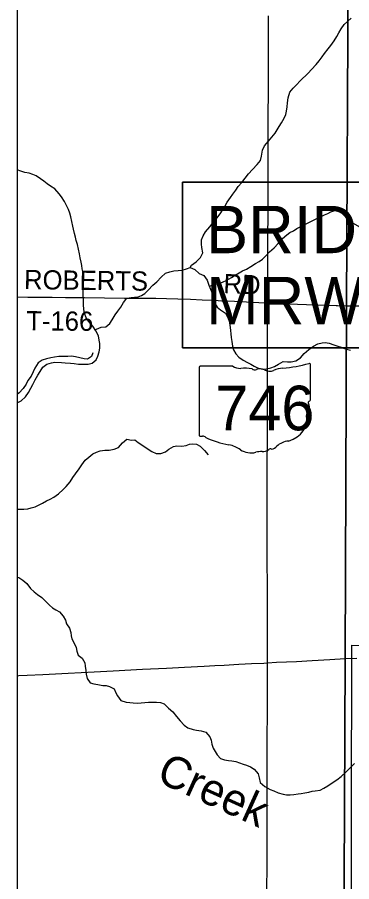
# Model space of a CAD drawing. Extents: x 0 to 34, y 0 to 22.
# Drawn here: x 2 to 2.991, y 17.017 to 19.573 of the extents above; entities that cross this region are included whole.
import ezdxf

# ---------------------------------------------------------------- set-up
doc = ezdxf.new("R2010")
doc.units = 0
for name, color, linetype in [('Default', 7, 'Continuous'), ('GM_X_County_Road', 7, 'Continuous'), ('GM_X_County_Road_Text', 7, 'Continuous'), ('GM_X_Interchange_Ramps', 7, 'Continuous'), ('GM_X_Minor_River', 7, 'Continuous'), ('GM_X_Rail_Line', 7, 'Continuous'), ('GM_X_Section', 7, 'Continuous'), ('GM_X_Section_Text', 7, 'Continuous'), ('GM_X_State_Location', 7, 'Continuous'), ('GM_X_Township_Road_Text', 7, 'Continuous'), ('GM_X_Unincorporated_Location', 7, 'Continuous'), ('SH_Border', 7, 'Continuous'), ('SH_Text', 7, 'Continuous')]:
    doc.layers.add(name, color=color, linetype=linetype)

msp = doc.modelspace()

# ---------------------------------------------------------------- linework, layer by layer
at = {"layer": 'Default'}
for points in [[(2.9623, 15.7101), (2.9708, 17.6769), (2.9753, 18.7199), (2.9796, 19.7242), (2.9904, 20.3395), (2.984, 20.7397), (2.9842, 20.8), (2, 20.8), (2, 15.7064)], [(8.1282, 20.8), (2.9842, 20.8), (2.984, 20.7397), (2.9904, 20.3395), (2.9796, 19.7242), (2.9753, 18.7199), (2.9708, 17.6769), (2.9623, 15.7101)]]:
    msp.add_lwpolyline(points, dxfattribs=at)
at = {"layer": 'GM_X_County_Road'}
for points in [[(2.741, 17.664), (2.741, 17.674), (2.7411, 17.6872), (2.7411, 17.7151), (2.7411, 17.7742), (2.7408, 17.8426), (2.7407, 17.8799), (2.7399, 17.9763), (2.7398, 18.0229), (2.7399, 18.1006), (2.7403, 18.1348), (2.7402, 18.1628), (2.7405, 18.2187), (2.7405, 18.2654), (2.7408, 18.312), (2.7409, 18.3618), (2.7412, 18.4426), (2.7413, 18.5203), (2.7414, 18.5732), (2.7415, 18.6074), (2.7413, 18.6416), (2.7414, 18.71), (2.7416, 18.7283), (2.7417, 18.7597), (2.7418, 18.8312), (2.7423, 18.8965), (2.7424, 18.94), (2.7426, 18.9742), (2.7427, 19.0271), (2.7428, 19.1079), (2.743, 19.1514), (2.7429, 19.1856), (2.7434, 19.2229), (2.7434, 19.2944), (2.7438, 19.341), (2.7437, 19.3939), (2.7437, 19.4188), (2.7441, 19.4623), (2.7444, 19.5245), (2.7443, 19.5586), (2.7443, 19.5773)], [(2, 17.6259), (2.0049, 17.6262), (2.0297, 17.6276), (2.0762, 17.6298), (2.1506, 17.6338), (2.2282, 17.6375), (2.284, 17.6403), (2.3709, 17.6449), (2.4422, 17.6484), (2.4949, 17.6511), (2.5539, 17.6543), (2.5848, 17.6559), (2.6128, 17.6576), (2.6562, 17.6597), (2.6934, 17.6617), (2.7306, 17.6634), (2.741, 17.664), (2.7678, 17.6656), (2.8268, 17.6684), (2.8733, 17.6713), (2.926, 17.674), (2.971, 17.6764)], [(2.971, 17.6764), (3.0056, 17.6782)], [(2.7394, 16.9815), (2.7404, 17.0747), (2.7402, 17.112), (2.74, 17.1369), (2.7401, 17.199), (2.7399, 17.2425), (2.7399, 17.2736), (2.7399, 17.3046), (2.74, 17.3637), (2.7402, 17.3885), (2.7404, 17.4165), (2.7405, 17.4538), (2.7406, 17.5035), (2.7407, 17.5408), (2.7408, 17.5998), (2.7412, 17.6321), (2.741, 17.6525), (2.741, 17.664)]]:
    msp.add_lwpolyline(points, dxfattribs=at)
at = {"layer": 'GM_X_Interchange_Ramps'}
for points in [[(2, 18.7465), (2.0314, 18.746), (2.1029, 18.7451), (2.1433, 18.7446), (2.1992, 18.7441), (2.3173, 18.7425), (2.3577, 18.7424), (2.3857, 18.7424), (2.4105, 18.7422), (2.4416, 18.7414), (2.4758, 18.7406), (2.5131, 18.7394), (2.5473, 18.7381), (2.5845, 18.7362), (2.6062, 18.735), (2.6435, 18.7332), (2.7335, 18.7286), (2.7416, 18.7283)], [(2.7416, 18.7283), (2.7614, 18.7274), (2.8298, 18.725), (2.9105, 18.7218), (2.9447, 18.7205), (2.9484, 18.7204), (2.9755, 18.7194)], [(2.9755, 18.7194), (3.0788, 18.7203), (3.1471, 18.7218), (3.2434, 18.7239), (3.2538, 18.7242)]]:
    msp.add_lwpolyline(points, dxfattribs=at)
at = {"layer": 'GM_X_Rail_Line'}
msp.add_lwpolyline([(2.489, 19.0856), (4.2244, 19.0856), (4.2244, 18.5956), (2.489, 18.5956)], close=True, dxfattribs=at)
at = {"layer": 'GM_X_Section'}
for points in [[(2.5122, 18.8334), (2.5161, 18.8406), (2.5295, 18.8502), (2.5426, 18.8633), (2.5493, 18.8762), (2.5468, 18.8921), (2.5454, 18.9024), (2.5452, 18.9149), (2.5503, 18.9274), (2.5577, 18.939), (2.5704, 18.954), (2.5804, 18.966), (2.5912, 18.9788), (2.6009, 18.9919), (2.6083, 19.0028), (2.6149, 19.0134), (2.6219, 19.0269), (2.6312, 19.0405), (2.6385, 19.0506), (2.647, 19.0622), (2.6547, 19.0724), (2.6655, 19.0848), (2.6748, 19.0972), (2.6845, 19.1099), (2.6968, 19.123), (2.7103, 19.138), (2.7199, 19.15), (2.7231, 19.1621), (2.7264, 19.1799), (2.7319, 19.1928), (2.7438, 19.207), (2.7535, 19.219), (2.7635, 19.2306), (2.7697, 19.2404), (2.7755, 19.2502), (2.7829, 19.2615), (2.7907, 19.2747), (2.7958, 19.2856), (2.7978, 19.2954), (2.7991, 19.3083), (2.8, 19.3201), (2.8021, 19.3352), (2.8073, 19.3515), (2.8169, 19.3638), (2.8265, 19.3736), (2.8377, 19.3852), (2.8612, 19.408), (2.8716, 19.4189), (2.885, 19.4339), (2.8943, 19.4444), (2.9032, 19.4564), (2.9101, 19.4662), (2.921, 19.48), (2.9287, 19.4902), (2.9383, 19.5033), (2.9465, 19.5161), (2.9527, 19.5274), (2.9589, 19.5391), (2.9686, 19.5515), (2.9892, 19.5709)], [(2.5689, 18.7779), (2.5806, 18.7824), (2.5935, 18.7853), (2.6076, 18.7896), (2.621, 18.7959), (2.6348, 18.8033), (2.6451, 18.8104), (2.657, 18.8178), (2.6673, 18.8233), (2.6784, 18.8285), (2.6921, 18.8359), (2.7059, 18.8448), (2.7162, 18.8508), (2.7262, 18.8582), (2.7377, 18.8694), (2.7474, 18.8792), (2.7604, 18.8919), (2.7727, 18.9046), (2.7855, 18.9189), (2.7981, 18.9297), (2.8077, 18.9364), (2.8184, 18.942), (2.8284, 18.9483), (2.8383, 18.9531), (2.852, 18.9601), (2.862, 18.9653), (2.8754, 18.9723), (2.8868, 18.9782), (2.8971, 18.9822), (2.9094, 18.9893), (2.9193, 18.9933), (2.9288, 18.9978), (2.9406, 19.0018), (2.9543, 19.0039), (2.9644, 18.9912), (2.9875, 18.9675)], [(2.9875, 18.9685), (3.0137, 18.9534)], [(2.2312, 18.6485), (2.235, 18.6509), (2.2484, 18.6571), (2.2625, 18.6577), (2.2744, 18.6674), (2.2813, 18.6787), (2.2903, 18.693), (2.2976, 18.7039), (2.3065, 18.7163), (2.3151, 18.7302), (2.3247, 18.743), (2.3369, 18.7447), (2.3475, 18.7453), (2.3582, 18.7467), (2.3677, 18.75), (2.3776, 18.7559), (2.3873, 18.7664), (2.4015, 18.7806), (2.413, 18.7907), (2.4265, 18.805), (2.4388, 18.8162), (2.4514, 18.8209), (2.4639, 18.8234), (2.4761, 18.8248), (2.4882, 18.8258), (2.5016, 18.8294), (2.5122, 18.8334), (2.5258, 18.8272), (2.5386, 18.816), (2.5529, 18.8097), (2.5622, 18.7956), (2.5677, 18.7807), (2.5725, 18.7696), (2.5769, 18.7574), (2.5805, 18.746), (2.5834, 18.7365), (2.5863, 18.7262), (2.5922, 18.7162), (2.602, 18.7085), (2.6163, 18.6985), (2.6241, 18.6855), (2.6273, 18.6748), (2.6298, 18.6634), (2.6319, 18.6474), (2.6325, 18.6375), (2.6339, 18.6258), (2.6352, 18.6144), (2.6373, 18.6007), (2.6402, 18.5896), (2.6473, 18.5782), (2.6562, 18.5678), (2.669, 18.5593), (2.6822, 18.5523), (2.692, 18.5476), (2.7018, 18.5414), (2.7116, 18.5363), (2.7248, 18.5327), (2.7381, 18.5333), (2.751, 18.5362), (2.7617, 18.5406), (2.774, 18.5476), (2.7877, 18.5554), (2.8006, 18.5545), (2.8112, 18.5539), (2.8249, 18.5568), (2.8387, 18.5665), (2.8499, 18.5785), (2.863, 18.5904), (2.8771, 18.6009), (2.8901, 18.6071), (2.9027, 18.61), (2.9122, 18.611), (2.9239, 18.6093), (2.9375, 18.6046), (2.9492, 18.601), (2.9594, 18.5975), (2.9715, 18.5931), (2.9864, 18.5885)], [(2, 18.1182), (2.0036, 18.1183), (2.0195, 18.1181), (2.0313, 18.1195), (2.0416, 18.1223), (2.0526, 18.1256), (2.0629, 18.13), (2.0744, 18.1363), (2.087, 18.1434), (2.0973, 18.1485), (2.1084, 18.1541), (2.1226, 18.1637), (2.1356, 18.1765), (2.1453, 18.1858), (2.1564, 18.1993), (2.1646, 18.2121), (2.1723, 18.223), (2.1835, 18.2377), (2.1909, 18.2501), (2.2009, 18.2632), (2.2121, 18.2726), (2.224, 18.2819), (2.2343, 18.2874), (2.2457, 18.2911), (2.2598, 18.2928), (2.2723, 18.2934), (2.2868, 18.2955), (2.3001, 18.3013), (2.3121, 18.3148), (2.324, 18.3257), (2.338, 18.3221), (2.3478, 18.3231), (2.3576, 18.3157), (2.3719, 18.3064), (2.3851, 18.2983), (2.3986, 18.289), (2.4114, 18.2835), (2.4251, 18.283), (2.4392, 18.2881), (2.4492, 18.2959), (2.4626, 18.3041), (2.4721, 18.3055), (2.4869, 18.3049), (2.5002, 18.307), (2.5105, 18.3103), (2.5203, 18.312), (2.5313, 18.3107), (2.5415, 18.3049), (2.5542, 18.2922), (2.5658, 18.2796)], [(2, 17.9178), (2.005, 17.9165), (2.0167, 17.9083), (2.0283, 17.8983), (2.0391, 17.8841), (2.0496, 17.8741), (2.0597, 17.866), (2.0725, 17.8575), (2.095, 17.8344), (2.1047, 17.8263), (2.1145, 17.8209), (2.1254, 17.8147), (2.1363, 17.8024), (2.1429, 17.7898), (2.1462, 17.7795), (2.1544, 17.7661), (2.1584, 17.7539), (2.1598, 17.7444), (2.1619, 17.7349), (2.1671, 17.7238), (2.1745, 17.7093), (2.1766, 17.699), (2.1806, 17.6868), (2.1926, 17.6776), (2.2, 17.6638), (2.2014, 17.6539), (2.2028, 17.6418), (2.2041, 17.6304), (2.207, 17.6182), (2.2159, 17.6048), (2.2265, 17.6016), (2.2386, 17.5999), (2.2538, 17.5975), (2.2636, 17.5966), (2.2735, 17.5942), (2.287, 17.5868), (2.2922, 17.5757), (2.2966, 17.5662), (2.307, 17.5527), (2.3225, 17.548), (2.3335, 17.5463), (2.343, 17.5454), (2.3547, 17.5445), (2.3665, 17.5455), (2.3779, 17.5465), (2.3882, 17.5475), (2.3992, 17.5477)], [(2.3992, 17.5477), (2.4121, 17.5479), (2.4246, 17.5466), (2.4352, 17.543), (2.4483, 17.53), (2.4603, 17.5196), (2.4718, 17.5058), (2.4827, 17.4923), (2.4939, 17.4797), (2.5048, 17.4719), (2.521, 17.4668), (2.5312, 17.4651), (2.5445, 17.4634), (2.5581, 17.4591), (2.5704, 17.4456), (2.5745, 17.4353), (2.5766, 17.4232), (2.5806, 17.4117), (2.5858, 17.4014), (2.5925, 17.3918), (2.6018, 17.3811), (2.6135, 17.3768), (2.626, 17.3751), (2.6359, 17.3742), (2.6472, 17.3721), (2.6688, 17.3646), (2.6793, 17.3611), (2.691, 17.356), (2.7012, 17.3498), (2.7131, 17.336), (2.7164, 17.3238), (2.7196, 17.3104), (2.7331, 17.2981), (2.7489, 17.2899), (2.7595, 17.2856), (2.7731, 17.2798), (2.7875, 17.2754), (2.7977, 17.2734), (2.8087, 17.2732), (2.8193, 17.2742), (2.8315, 17.2763), (2.841, 17.2781), (2.852, 17.2798), (2.8631, 17.282), (2.8729, 17.2841), (2.8824, 17.2851), (2.8969, 17.2876), (2.9076, 17.2931), (2.9195, 17.3002), (2.9329, 17.3087), (2.9463, 17.3176), (2.9593, 17.3277), (2.9727, 17.3404), (2.9802, 17.3473)], [(2.9802, 17.3473), (2.9985, 17.3662)]]:
    msp.add_lwpolyline(points, dxfattribs=at)
at = {"layer": 'GM_X_Section_Text'}
for points in [[(2.2401, 18.6314), (2.2327, 18.6463), (2.2238, 18.6594), (2.2107, 18.6743), (2.2044, 18.6847), (2.1996, 18.6984), (2.1975, 18.7094), (2.1962, 18.7239), (2.1964, 18.7371), (2.1955, 18.7538), (2.1952, 18.7648), (2.195, 18.7743), (2.1955, 18.7842), (2.1968, 18.7948), (2.197, 18.8077), (2.1948, 18.8172), (2.1919, 18.829), (2.1913, 18.8389), (2.1892, 18.8488), (2.1867, 18.8617), (2.1842, 18.8735), (2.1813, 18.8872), (2.1781, 18.9009), (2.1749, 18.9131), (2.1723, 18.9233), (2.1695, 18.934), (2.1666, 18.9462), (2.1644, 18.9557), (2.162, 18.969), (2.1584, 18.9827), (2.1555, 18.9938), (2.1514, 19.0044), (2.1452, 19.0182), (2.14, 19.0281), (2.1311, 19.0419), (2.1244, 19.0515), (2.1117, 19.0664), (2.0989, 19.0742), (2.0887, 19.0808), (2.079, 19.0885), (2.0692, 19.0958), (2.0564, 19.104), (2.0459, 19.1087), (2.0349, 19.1118), (2.0228, 19.1147), (2.0107, 19.1179), (2, 19.122)], [(2, 18.4332), (2.0117, 18.4391), (2.024, 18.4504), (2.0337, 18.4635), (2.0403, 18.4763), (2.0458, 18.4869), (2.0535, 18.5008), (2.0609, 18.5144), (2.0675, 18.526), (2.0757, 18.5381), (2.0872, 18.5478), (2.1013, 18.5514), (2.1115, 18.5528), (2.1309, 18.5525), (2.1423, 18.5516), (2.1574, 18.5499), (2.1684, 18.549), (2.1813, 18.5476), (2.1953, 18.5475), (2.2101, 18.5473), (2.2223, 18.5501), (2.2334, 18.5602), (2.2385, 18.5711), (2.2425, 18.5836), (2.2445, 18.5942), (2.2443, 18.6083), (2.243, 18.6185), (2.2401, 18.6314)], [(2.2235, 18.5805), (2.2203, 18.5703), (2.2077, 18.5625), (2.1982, 18.5633), (2.185, 18.5662), (2.1721, 18.5694), (2.1611, 18.5711), (2.1497, 18.5705), (2.1364, 18.5703), (2.1232, 18.5697), (2.1106, 18.5683), (2.0996, 18.5658), (2.087, 18.5629), (2.0741, 18.5593), (2.0618, 18.5515), (2.0517, 18.5354), (2.0467, 18.5248), (2.0412, 18.512), (2.0315, 18.4992), (2.026, 18.4883), (2.0179, 18.4751), (2.0056, 18.4624), (2, 18.4578)]]:
    msp.add_lwpolyline(points, dxfattribs=at)
at = {"layer": 'GM_X_State_Location'}
for p, q in [((2.5385, 18.5378), (2.5385, 18.3376)), ((2.6383, 18.5412), (2.5418, 18.5412)), ((2.8681, 18.4415), (2.8681, 18.5462)), ((2.8681, 18.4415), (2.8681, 18.4415))]:
    msp.add_line(p, q, dxfattribs=at)
for centre, major_axis, start_param, end_param in [((2.5423, 18.5382), (0.00382, 0), 1.712693, 3.28349), ((2.6613, 18.5644), (0.037, 0), 4.042523, 4.731795), ((2.6736, 18.4289), (0.133, 0), 1.404758, 1.657858), ((2.7194, 18.5161), (0.0222, 0), 0.950623, 2.079405), ((2.7953, 18.4801), (0.0703, 0), 1.699011, 2.107814), ((2.7507, 18.814), (0.3495, 0), 4.814394, 5.042369), ((2.8645, 18.5466), (0.00367, 0), 6.141152, 7.989035), ((2.7037, 18.5392), (0.0107, 0), 3.836095, 5.185415), ((2.7481, 18.5478), (0.0267, 0), 4.081561, 5.145723), ((2.8673, 18.4338), (0.00568, 0), 1.883978, 3.671073), ((2.8642, 18.4411), (0.00393, 0), 5.05454, 6.418171), ((2.8813, 18.3977), (0.0248, 0), 2.387724, 3.262537), ((2.8311, 18.4206), (0.0341, 0), 5.934695, 6.695948), ((2.7703, 18.3844), (0.0874, 0), 5.101752, 6.440018), ((2.5423, 18.3372), (0.00385, 0), 3.00124, 4.508301), ((2.5429, 18.3577), (0.0294, 0), 4.665946, 4.897461), ((2.5489, 18.3261), (0.0106, 0), 0.519207, 1.627899), ((2.6828, 18.5059), (0.2524, 0), 4.195997, 4.488961), ((2.6075, 18.2477), (0.079, 0), 0.823519, 1.323587), ((2.8072, 18.2815), (0.0479, 0), 1.647645, 2.488434), ((2.6929, 18.3251), (0.0501, 0), 4.026481, 4.996735), ((2.7219, 18.2559), (0.0412, 0), 1.495662, 1.94098), ((2.7255, 18.3101), (0.0267, 0), 4.691044, 5.507374), ((2.7497, 18.2907), (0.00752, 0), 1.147584, 2.315152), ((2.7465, 18.3182), (0.0282, 0), 4.937069, 5.64225)]:
    msp.add_ellipse(centre, major_axis=major_axis, ratio=0.8, start_param=start_param, end_param=end_param, dxfattribs=at)
at = {"layer": 'GM_X_Unincorporated_Location'}
msp.add_lwpolyline([(4.0116, 17.7079), (3.9996, 16.6997), (2.9891, 16.7122), (2.9907, 17.7166)], close=True, dxfattribs=at)
at = {"layer": 'SH_Border'}
msp.add_lwpolyline([(2.489, 18.5956), (4.2244, 18.5956), (4.2244, 19.0856), (2.489, 19.0856)], close=True, dxfattribs=at)
at = {"layer": 'SH_Text'}
for points in [[(2.9842, 20.8), (2, 20.8), (2, 14), (2.9377, 14), (2.9479, 14.7065), (2.9623, 15.7101), (2.9708, 17.6769), (2.9753, 18.7199), (2.9796, 19.7242), (2.9904, 20.3395), (2.984, 20.7397)], [(2.9377, 14), (8.8, 14), (8.8, 20.8), (2.9842, 20.8), (2.984, 20.7397), (2.9904, 20.3395), (2.9796, 19.7242), (2.9753, 18.7199), (2.9708, 17.6769), (2.9623, 15.7101), (2.9479, 14.7065)]]:
    msp.add_lwpolyline(points, close=True, dxfattribs=at)

# ---------------------------------------------------------------- texts
at = {"layer": 'GM_X_County_Road_Text'}
for s, rotation, p in [('ROBERTS', 359.2384, (2.0198, 18.7694)), ('RD', 357.5333, (2.6096, 18.7577)), ('T-166', 359.4474, (2.0264, 18.6476))]:
    msp.add_text(s, height=0.05682, rotation=rotation, dxfattribs=at).set_placement(p)
at = {"layer": 'GM_X_Minor_River'}
msp.add_text('Creek', height=0.09472, rotation=335.6132, dxfattribs=at).set_placement((2.4083, 17.3152))
at = {"layer": 'GM_X_State_Location'}
msp.add_text('746', height=0.13184, dxfattribs=at).set_placement((2.586, 18.3518))
at = {"layer": 'GM_X_Township_Road_Text'}
msp.add_text('746', height=0.000189, rotation=0, dxfattribs=at).set_placement((2.6328, 18.4106))
for s in ['s', 'r']:
    msp.add_text(s, height=0.000189, dxfattribs=at).set_placement((2.6996, 18.4244))
at = {"layer": 'SH_Border'}
for s, p in [('BRIDGE NO. ', (2.559, 18.8756)), ('MRW-95-1.92', (2.559, 18.6656))]:
    msp.add_text(s, height=0.14, dxfattribs=at).set_placement(p)

doc.saveas('drawing.dxf')
